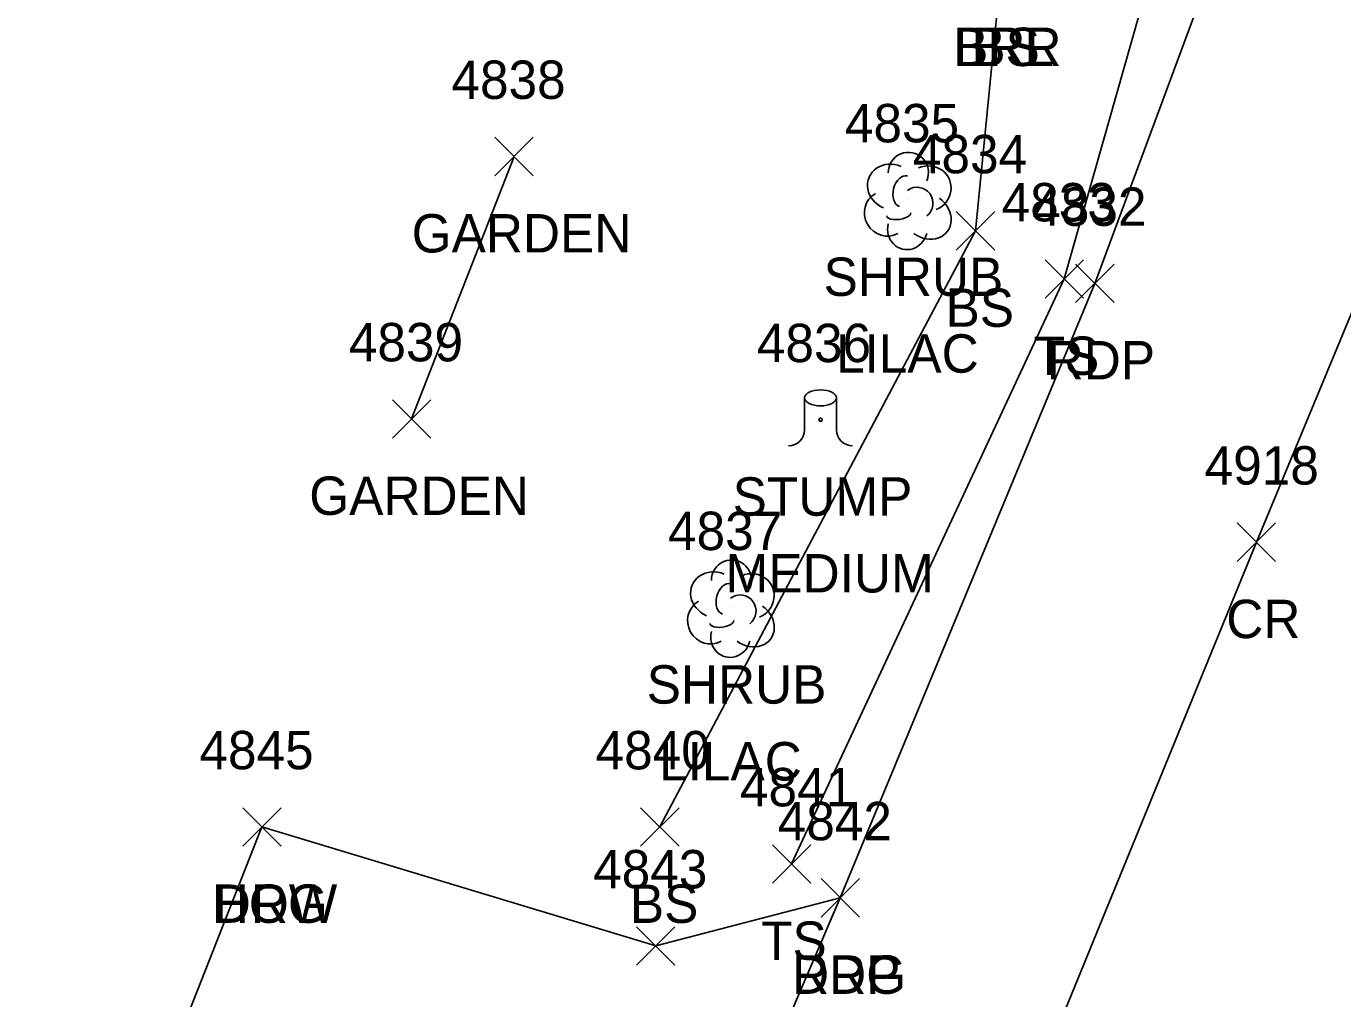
# Model space of a CAD drawing. Extents: x 1653135 to 1655489, y 602711 to 605684.
# Drawn here: x 1653445.9 to 1653514.5, y 604710.6 to 604761.3 of the extents above; entities that cross this region are included whole.
import ezdxf

# ---------------------------------------------------------------- set-up
doc = ezdxf.new("R2010")
doc.units = 0
for name, color, linetype in [('L_A', 7, 'Continuous'), ('L_C', 7, 'Continuous'), ('L_I', 7, 'Continuous'), ('L_TIC', 7, 'Continuous'), ('LAPB', 7, 'Continuous'), ('LBC', 7, 'Continuous'), ('LELB', 7, 'Continuous'), ('LSH', 7, 'Continuous'), ('LTS', 7, 'Continuous'), ('P_A', 7, 'Continuous'), ('P_I', 7, 'Continuous'), ('P_TIC', 7, 'Continuous'), ('PET', 7, 'Continuous'), ('PRC', 7, 'Continuous'), ('R_A', 7, 'Continuous'), ('R_I', 7, 'Continuous'), ('R_TIC', 7, 'Continuous'), ('RDG', 7, 'Continuous')]:
    doc.layers.add(name, color=color, linetype=linetype)

msp = doc.modelspace()

# ---------------------------------------------------------------- linework, layer by layer
at = {"layer": 'L_TIC'}
for points in [[(1653470.323, 604753.486), (1653472.323, 604755.486)], [(1653472.323, 604753.486), (1653470.323, 604755.486)], [(1653470.323, 604753.486), (1653472.323, 604755.486)], [(1653472.323, 604753.486), (1653470.323, 604755.486)], [(1653494.359, 604749.614), (1653496.359, 604751.614)], [(1653496.359, 604749.614), (1653494.359, 604751.614)], [(1653494.359, 604749.614), (1653496.359, 604751.614)], [(1653496.359, 604749.614), (1653494.359, 604751.614)], [(1653498.98, 604747.106), (1653500.98, 604749.106)], [(1653500.98, 604747.106), (1653498.98, 604749.106)], [(1653498.98, 604747.106), (1653500.98, 604749.106)], [(1653500.98, 604747.106), (1653498.98, 604749.106)], [(1653464.987, 604739.815), (1653466.987, 604741.815)], [(1653466.987, 604739.815), (1653464.987, 604741.815)], [(1653464.987, 604739.815), (1653466.987, 604741.815)], [(1653466.987, 604739.815), (1653464.987, 604741.815)], [(1653457.195, 604718.563), (1653459.195, 604720.563)], [(1653459.195, 604718.563), (1653457.195, 604720.563)], [(1653457.195, 604718.563), (1653459.195, 604720.563)], [(1653459.195, 604718.563), (1653457.195, 604720.563)], [(1653477.917, 604718.559), (1653479.917, 604720.559)], [(1653479.917, 604718.559), (1653477.917, 604720.559)], [(1653477.917, 604718.559), (1653479.917, 604720.559)], [(1653479.917, 604718.559), (1653477.917, 604720.559)], [(1653484.782, 604716.633), (1653486.782, 604718.633)], [(1653486.782, 604716.633), (1653484.782, 604718.633)], [(1653484.782, 604716.633), (1653486.782, 604718.633)], [(1653486.782, 604716.633), (1653484.782, 604718.633)]]:
    msp.add_lwpolyline(points, dxfattribs=at)
at = {"layer": 'LAPB'}
msp.add_lwpolyline([(1653471.323, 604754.486), (1653465.987, 604740.815)], dxfattribs=at)
at = {"layer": 'LBC'}
msp.add_lwpolyline([(1653458.195, 604719.563), (1653451.866, 604703.506), (1653447.898, 604692.645), (1653457.038, 604689.383), (1653453.437, 604680.785), (1653451.891, 604675.708), (1653445.92, 604659.798)], dxfattribs=at)
at = {"layer": 'LELB'}
for points in [[(1653496.628, 604781.494), (1653498.565, 604781.126), (1653500.621, 604777.671), (1653501.108, 604772.307), (1653506.231, 604770.152), (1653499.98, 604748.106), (1653485.782, 604717.633)], [(1653496.703, 604764.199), (1653495.359, 604750.614), (1653478.917, 604719.559)]]:
    msp.add_lwpolyline(points, dxfattribs=at)
at = {"layer": 'LSH'}
for p, q in [((1653491.816, 604752.224), (1653491.816, 604752.224)), ((1653491.816, 604752.224), (1653491.816, 604752.224)), ((1653482.603, 604730.983), (1653482.603, 604730.983)), ((1653482.603, 604730.983), (1653482.603, 604730.983))]:
    msp.add_line(p, q, dxfattribs=at)
for centre in [(1653491.863, 604753.658), (1653482.65, 604732.417)]:
    msp.add_arc(centre, 1.047, 335.52715, 180.95627, dxfattribs=at)
for centre, major_axis, ratio, start_param, end_param in [((1653491.024, 604752.89), (1.21, -0.512), 0.895232, 1.570796, 4.712389), ((1653492.857, 604752.807), (-1.141, -0.483), 0.949671, 1.570796, 4.712389), ((1653491.607, 604752.682), (-0.208, -0.792), 0.645439, 3.141593, 6.283185), ((1653490.733, 604751.515), (0.584, -1.042), 0.959034, 3.141593, 6.283185), ((1653492.316, 604752.057), (-0.5, 0.667), 0.989748, 3.141593, 6.283185), ((1653492.816, 604751.391), (-1.09, 0.792), 0.841452, 1.570796, 4.712389), ((1653491.358, 604751.474), (-0.625, -0.083), 0.423636, 0, 3.141593), ((1653491.816, 604750.724), (0.265, 1.061), 0.942809, 1.570796, 4.712389), ((1653481.811, 604731.649), (1.21, -0.512), 0.895232, 1.570796, 4.712389), ((1653483.645, 604731.566), (-1.141, -0.483), 0.949671, 1.570796, 4.712389), ((1653482.395, 604731.441), (-0.208, -0.792), 0.645439, 3.141593, 6.283185), ((1653481.52, 604730.274), (0.584, -1.042), 0.959034, 3.141593, 6.283185), ((1653483.103, 604730.816), (-0.5, 0.667), 0.989748, 3.141593, 6.283185), ((1653483.603, 604730.149), (-1.09, 0.792), 0.841452, 1.570796, 4.712389), ((1653482.145, 604730.233), (-0.625, -0.083), 0.423636, 0, 3.141593), ((1653482.604, 604729.483), (0.265, 1.061), 0.942809, 1.570796, 4.712389)]:
    msp.add_ellipse(centre, major_axis=major_axis, ratio=ratio, start_param=start_param, end_param=end_param, dxfattribs=at)
at = {"layer": 'LTS'}
for p, q in [((1653486.457, 604741.914), (1653486.457, 604740.248)), ((1653488.123, 604741.748), (1653488.123, 604741.914)), ((1653488.123, 604741.914), (1653488.123, 604740.248)), ((1653487.29, 604740.772), (1653487.29, 604740.772)), ((1653487.29, 604740.772), (1653487.29, 604740.772)), ((1653487.29, 604740.748), (1653487.29, 604740.748))]:
    msp.add_line(p, q, dxfattribs=at)
msp.add_circle((1653487.29, 604740.772), 0.0833, dxfattribs=at)
for centre, start, end in [((1653485.623, 604740.248), 270, 360), ((1653488.957, 604740.248), 180, 270)]:
    msp.add_arc(centre, 0.833, start, end, dxfattribs=at)
msp.add_ellipse((1653487.29, 604741.914), major_axis=(-0.833, 0), ratio=0.5, dxfattribs=at)
at = {"layer": 'P_TIC'}
for points in [[(1653500.575, 604746.875), (1653502.575, 604748.875)], [(1653502.575, 604746.875), (1653500.575, 604748.875)], [(1653500.575, 604746.875), (1653502.575, 604748.875)], [(1653502.575, 604746.875), (1653500.575, 604748.875)], [(1653508.987, 604733.396), (1653510.987, 604735.396)], [(1653510.987, 604733.396), (1653508.987, 604735.396)], [(1653508.987, 604733.396), (1653510.987, 604735.396)], [(1653510.987, 604733.396), (1653508.987, 604735.396)], [(1653487.316, 604714.865), (1653489.316, 604716.865)], [(1653489.316, 604714.865), (1653487.316, 604716.865)], [(1653487.316, 604714.865), (1653489.316, 604716.865)], [(1653489.316, 604714.865), (1653487.316, 604716.865)]]:
    msp.add_lwpolyline(points, dxfattribs=at)
at = {"layer": 'PET'}
msp.add_lwpolyline([(1653633.646, 605084.486), (1653621.617, 605050.514), (1653609.161, 605016.811), (1653593.415, 604976.628), (1653581.247, 604945.503), (1653566.997, 604910.296), (1653555.966, 604883.53), (1653545.833, 604858.095), (1653540.542, 604853.303), (1653537.113, 604852.972), (1653527.536, 604814.719), (1653509.397, 604769.005), (1653501.575, 604747.875), (1653488.316, 604715.865), (1653477.29, 604690.088), (1653463.629, 604652.761)], dxfattribs=at)
at = {"layer": 'PRC'}
msp.add_lwpolyline([(1653642.794, 605070.13), (1653630.687, 605038.22), (1653617.604, 605002.899), (1653603.985, 604967.155), (1653594.728, 604943.347), (1653580.105, 604906.755), (1653569.49, 604880.56), (1653554.212, 604842.781), (1653538.782, 604804.489), (1653523.366, 604766.647), (1653509.987, 604734.396), (1653497.08, 604702.808), (1653488.718, 604682.378), (1653475.021, 604648.225)], dxfattribs=at)
at = {"layer": 'R_TIC'}
for points in [[(1653457.195, 604718.563), (1653459.195, 604720.563)], [(1653459.195, 604718.563), (1653457.195, 604720.563)], [(1653457.195, 604718.563), (1653459.195, 604720.563)], [(1653459.195, 604718.563), (1653457.195, 604720.563)], [(1653487.316, 604714.865), (1653489.316, 604716.865)], [(1653489.316, 604714.865), (1653487.316, 604716.865)], [(1653487.316, 604714.865), (1653489.316, 604716.865)], [(1653489.316, 604714.865), (1653487.316, 604716.865)], [(1653477.703, 604712.358), (1653479.703, 604714.358)], [(1653479.703, 604712.358), (1653477.703, 604714.358)], [(1653477.703, 604712.358), (1653479.703, 604714.358)], [(1653479.703, 604712.358), (1653477.703, 604714.358)]]:
    msp.add_lwpolyline(points, dxfattribs=at)
at = {"layer": 'RDG'}
msp.add_lwpolyline([(1653488.316, 604715.865), (1653478.703, 604713.358), (1653458.195, 604719.563)], dxfattribs=at)

# ---------------------------------------------------------------- texts
at = {"layer": 'L_A'}
for s, p in [('BRR', (1653494.191, 604759.199)), ('BRR', (1653494.191, 604759.199)), ('BRL', (1653494.246, 604759.199)), ('BRL', (1653494.246, 604759.199)), ('BS', (1653495.144, 604759.199)), ('BS', (1653495.144, 604759.199)), ('GARDEN', (1653465.992, 604749.486)), ('GARDEN', (1653465.992, 604749.486)), ('SHRUB', (1653487.446, 604747.224)), ('BS', (1653493.8, 604745.614)), ('BS', (1653493.8, 604745.614)), ('TS', (1653498.389, 604743.106)), ('TS', (1653498.389, 604743.106)), ('GARDEN', (1653460.656, 604735.815)), ('GARDEN', (1653460.656, 604735.815)), ('STUMP', (1653482.711, 604735.774)), ('SHRUB', (1653478.233, 604725.983)), ('HOW', (1653455.58, 604714.563)), ('HOW', (1653455.58, 604714.563)), ('BS', (1653477.358, 604714.559)), ('BS', (1653477.358, 604714.559)), ('TS', (1653484.191, 604712.633)), ('TS', (1653484.191, 604712.633))]:
    msp.add_text(s, height=2, dxfattribs=at).set_placement(p)
at = {"layer": 'L_C'}
for s, p in [('LILAC', (1653488.092, 604743.224)), ('MEDIUM', (1653482.341, 604731.774)), ('LILAC', (1653478.879, 604721.983))]:
    msp.add_text(s, height=2, dxfattribs=at).set_placement(p)
at = {"layer": 'L_I'}
for s, p in [('4838', (1653468.063, 604757.486)), ('4838', (1653468.063, 604757.486)), ('4835', (1653488.556, 604755.224)), ('4834', (1653492.099, 604753.614)), ('4834', (1653492.099, 604753.614)), ('4833', (1653496.72, 604751.106)), ('4833', (1653496.72, 604751.106)), ('4839', (1653462.719, 604743.815)), ('4839', (1653462.719, 604743.815)), ('4836', (1653483.971, 604743.774)), ('4837', (1653479.344, 604733.983)), ('4845', (1653454.935, 604722.563)), ('4845', (1653454.935, 604722.563)), ('4840', (1653475.571, 604722.559)), ('4840', (1653475.571, 604722.559)), ('4841', (1653483.089, 604720.633)), ('4841', (1653483.089, 604720.633))]:
    msp.add_text(s, height=2, dxfattribs=at).set_placement(p)
at = {"layer": 'P_A'}
for s, p in [('RDP', (1653499.064, 604742.875)), ('RDP', (1653499.064, 604742.875)), ('CR', (1653508.42, 604729.396)), ('CR', (1653508.42, 604729.396)), ('RDP', (1653485.804, 604710.865)), ('RDP', (1653485.804, 604710.865))]:
    msp.add_text(s, height=2, dxfattribs=at).set_placement(p)
at = {"layer": 'P_I'}
for s, p in [('4832', (1653498.316, 604750.875)), ('4832', (1653498.316, 604750.875)), ('4918', (1653507.294, 604737.396)), ('4918', (1653507.294, 604737.396)), ('4842', (1653485.056, 604718.865)), ('4842', (1653485.056, 604718.865))]:
    msp.add_text(s, height=2, dxfattribs=at).set_placement(p)
at = {"layer": 'R_A'}
for p in [(1653455.683, 604714.563), (1653455.683, 604714.563), (1653485.804, 604710.865), (1653485.804, 604710.865)]:
    msp.add_text('DRG', height=2, dxfattribs=at).set_placement(p)
at = {"layer": 'R_I'}
for s, p in [('4845', (1653454.935, 604722.563)), ('4845', (1653454.935, 604722.563)), ('4842', (1653485.056, 604718.865)), ('4842', (1653485.056, 604718.865)), ('4843', (1653475.443, 604716.358)), ('4843', (1653475.443, 604716.358))]:
    msp.add_text(s, height=2, dxfattribs=at).set_placement(p)

doc.saveas('drawing.dxf')
